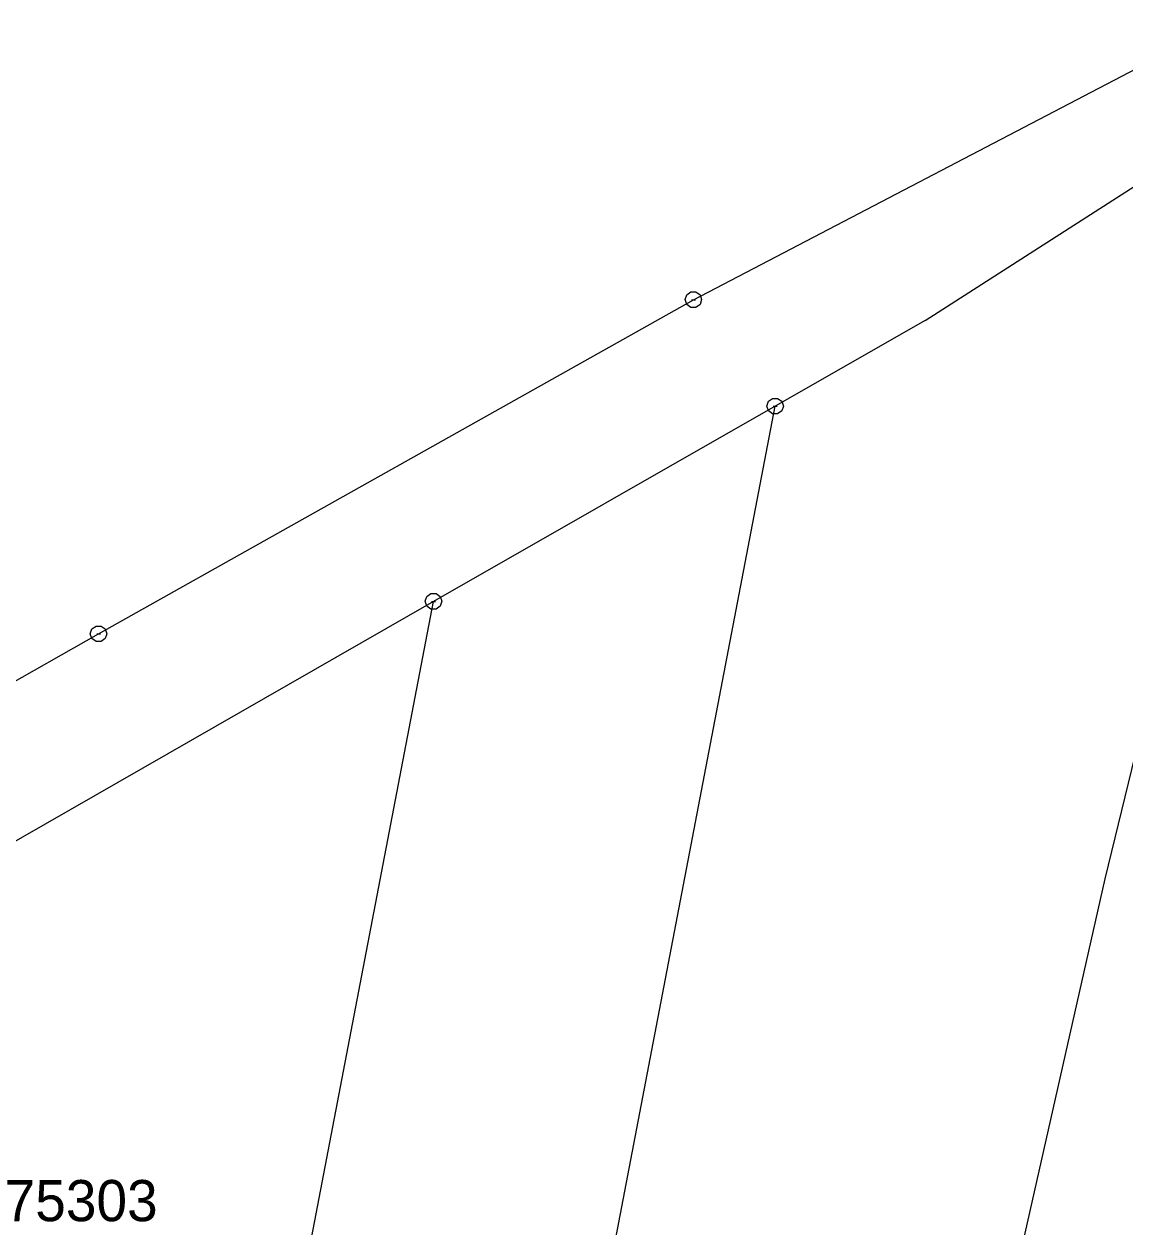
# Model space of a CAD drawing. Extents: x -760611 to -758411, y -1176479 to -1174807.
# Drawn here: x -759476.2 to -759409.4, y -1175181.7 to -1175108.7 of the extents above; entities that cross this region are included whole.
import ezdxf

# ---------------------------------------------------------------- set-up
doc = ezdxf.new("R2010")
doc.units = 0
for name, color, linetype in [('1', 7, 'Continuous'), ('11', 7, 'Continuous'), ('8', 7, 'Continuous')]:
    doc.layers.add(name, color=color, linetype=linetype)

msp = doc.modelspace()

# ---------------------------------------------------------------- linework, layer by layer
at = {"layer": '1'}
for p, q in [((-759435.58, -1175125.4), (-759403.51, -1175108.65)), ((-759421.5, -1175126.66), (-759402.6, -1175114.51)), ((-759410.58, -1175160.57), (-759400.38, -1175118.69)), ((-759471.7, -1175145.7), (-759435.58, -1175125.4)), ((-759421.5, -1175126.66), (-759430.62, -1175131.87)), ((-759458.35, -1175276.62), (-759430.62, -1175131.87)), ((-759430.62, -1175131.87), (-759451.36, -1175143.73)), ((-759451.36, -1175143.73), (-759493.7, -1175167.99)), ((-759476.73, -1175276.15), (-759451.36, -1175143.73)), ((-759497.47, -1175160.23), (-759471.7, -1175145.7)), ((-759418.48, -1175195.58), (-759410.58, -1175160.57))]:
    msp.add_line(p, q, dxfattribs=at)
at = {"layer": '8'}
for p, q in [((-759435.7, -1175125.4), (-759435.46, -1175125.4)), ((-759430.74, -1175131.87), (-759430.5, -1175131.87)), ((-759451.48, -1175143.73), (-759451.24, -1175143.73)), ((-759471.82, -1175145.7), (-759471.58, -1175145.7))]:
    msp.add_line(p, q, dxfattribs=at)
for points in [[(-759435.43, -1175124.92), (-759435.18, -1175125.1), (-759435.08, -1175125.39), (-759435.18, -1175125.68), (-759435.43, -1175125.86), (-759435.74, -1175125.86), (-759435.99, -1175125.68), (-759436.09, -1175125.39), (-759435.99, -1175125.1), (-759435.74, -1175124.92)], [(-759430.47, -1175131.39), (-759430.22, -1175131.57), (-759430.12, -1175131.86), (-759430.22, -1175132.15), (-759430.47, -1175132.33), (-759430.78, -1175132.33), (-759431.03, -1175132.15), (-759431.13, -1175131.86), (-759431.03, -1175131.57), (-759430.78, -1175131.39)], [(-759451.21, -1175143.25), (-759450.96, -1175143.43), (-759450.86, -1175143.72), (-759450.96, -1175144.01), (-759451.21, -1175144.19), (-759451.52, -1175144.19), (-759451.77, -1175144.01), (-759451.87, -1175143.72), (-759451.77, -1175143.43), (-759451.52, -1175143.25)], [(-759471.55, -1175145.22), (-759471.3, -1175145.4), (-759471.2, -1175145.69), (-759471.3, -1175145.98), (-759471.55, -1175146.16), (-759471.86, -1175146.16), (-759472.11, -1175145.98), (-759472.21, -1175145.69), (-759472.11, -1175145.4), (-759471.86, -1175145.22)]]:
    msp.add_lwpolyline(points, close=True, dxfattribs=at)

# ---------------------------------------------------------------- texts
at = {"layer": '11'}
msp.add_text('75303', height=2.5, dxfattribs=at).set_placement((-759477.412, -1175181.379))

doc.saveas('drawing.dxf')
